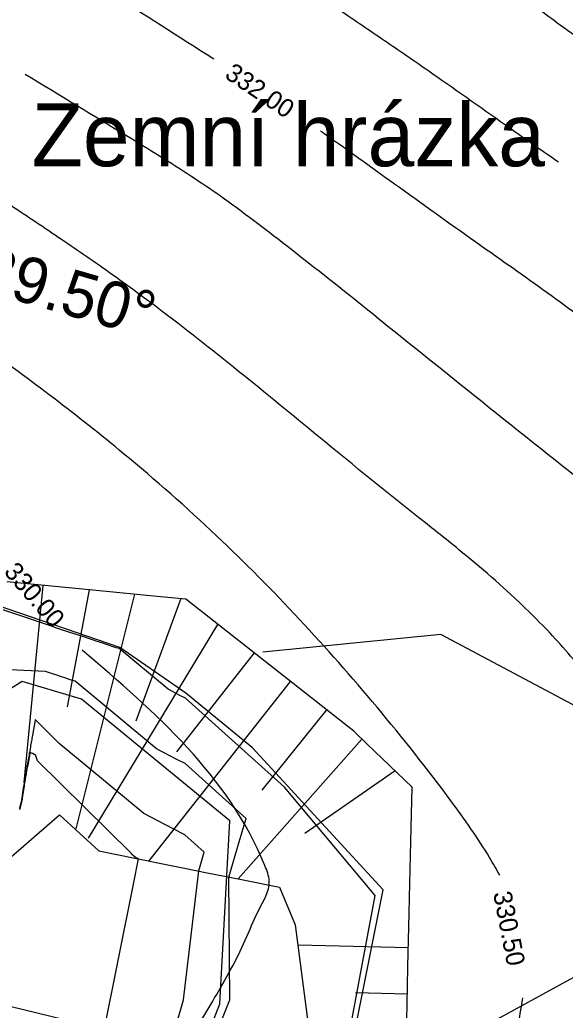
# Model space of a CAD drawing. Extents: x -564037 to -563827, y -1163561 to -1163412.
# Drawn here: x -563886.48 to -563871.67, y -1163493.12 to -1163466.24 of the extents above; entities that cross this region are included whole.
import ezdxf

# ---------------------------------------------------------------- set-up
doc = ezdxf.new("R2010")
doc.units = 0
for name, color, linetype in [('4', 7, 'Continuous'), ('5', 7, 'Continuous'), ('_popis staničení RT1', 7, 'Continuous'), ('Default', 7, 'Continuous'), ('Line', 7, 'Continuous'), ('Vrstva 24', 7, 'Continuous'), ('Vrstva 25', 7, 'Continuous'), ('Vrstva 26', 7, 'Continuous')]:
    doc.layers.add(name, color=color, linetype=linetype)

msp = doc.modelspace()

# ---------------------------------------------------------------- linework, layer by layer
for points in [[(-563900.324, -1163505.882), (-563892.678, -1163503.006), (-563888.735, -1163501.906), (-563886.271, -1163502.018), (-563883.536, -1163500.684), (-563878.095, -1163497.234), (-563876.621, -1163489.849), (-563880.163, -1163485.998), (-563881.977, -1163484.515), (-563883.765, -1163483.269), (-563890.133, -1163481.092), (-563891.974, -1163485.382), (-563895.143, -1163493.304), (-563898.704, -1163502.458), (-563900.439, -1163505.855)], [(-563887.058, -1163484.593), (-563887.855, -1163487.81), (-563890.21, -1163493.633), (-563891.581, -1163498.253), (-563891.461, -1163499.576), (-563890.275, -1163499.82), (-563886.599, -1163499.649), (-563882.84, -1163497.558), (-563881.049, -1163492.941), (-563880.784, -1163487.979), (-563884.81, -1163484.679), (-563886.418, -1163484.198)]]:
    msp.add_lwpolyline(points, close=True)
for points in [[(-563878.137, -1163496.97), (-563876.837, -1163490), (-563879.296, -1163487.066), (-563881.987, -1163484.651), (-563882.119, -1163484.582), (-563882.455, -1163484.408), (-563883.788, -1163483.304), (-563883.864, -1163483.279), (-563884.159, -1163483.181), (-563884.226, -1163483.159), (-563884.302, -1163483.134), (-563884.34, -1163483.121), (-563884.386, -1163483.106), (-563884.482, -1163483.074), (-563884.592, -1163483.038), (-563884.718, -1163482.996), (-563884.865, -1163482.947), (-563884.978, -1163482.91), (-563885.376, -1163482.786), (-563885.4, -1163482.777), (-563885.486, -1163482.747), (-563885.596, -1163482.707), (-563890.151, -1163481.173)], [(-563866.782, -1163487.32), (-563875.054, -1163482.917), (-563879.887, -1163483.398)], [(-563882.19, -1163496.364), (-563880.778, -1163492.835), (-563880.808, -1163489.502), (-563880.527, -1163488.546), (-563880.34, -1163487.91), (-563881.995, -1163486.424), (-563882.215, -1163486.31), (-563882.772, -1163486.021), (-563884.984, -1163484.19), (-563885.111, -1163484.148), (-563885.233, -1163484.108), (-563885.348, -1163484.069), (-563885.478, -1163484.026), (-563885.544, -1163484.004), (-563885.623, -1163483.978), (-563885.788, -1163483.923), (-563887.164, -1163483.863), (-563888.153, -1163487.579), (-563890.867, -1163493.518)], [(-563883.008, -1163496.199), (-563882.04, -1163492.836), (-563881.625, -1163489.337), (-563881.476, -1163488.829), (-563882.005, -1163488.354), (-563882.32, -1163488.191), (-563883.117, -1163487.777), (-563885.412, -1163485.878), (-563885.848, -1163485.443), (-563886.064, -1163485.228), (-563886.076, -1163485.297), (-563886.076, -1163485.299), (-563886.085, -1163485.349), (-563886.086, -1163485.357), (-563886.119, -1163485.544), (-563886.123, -1163485.565), (-563886.154, -1163485.739), (-563886.159, -1163485.771), (-563886.188, -1163485.934), (-563886.195, -1163485.977), (-563886.222, -1163486.129), (-563886.225, -1163486.143), (-563886.233, -1163486.193), (-563886.255, -1163486.313), (-563886.255, -1163486.317), (-563886.275, -1163486.425), (-563886.283, -1163486.475), (-563886.288, -1163486.503), (-563886.291, -1163486.518), (-563886.312, -1163486.636), (-563886.324, -1163486.708), (-563886.339, -1163486.796), (-563886.352, -1163486.873), (-563886.356, -1163486.898), (-563886.367, -1163486.965), (-563886.38, -1163487.043), (-563886.387, -1163487.088), (-563886.417, -1163487.278), (-563886.42, -1163487.295), (-563886.422, -1163487.306), (-563886.427, -1163487.341), (-563886.437, -1163487.403), (-563886.447, -1163487.469), (-563886.478, -1163487.59), (-563886.495, -1163487.654)], [(-563884.64, -1163495.87), (-563883.396, -1163489.693), (-563883.258, -1163489.008), (-563883.35, -1163488.961), (-563883.403, -1163488.916), (-563883.413, -1163488.906), (-563883.424, -1163488.896), (-563883.429, -1163488.891), (-563883.454, -1163488.866), (-563886.003, -1163486.346), (-563886.061, -1163486.188), (-563886.092, -1163486.174), (-563886.139, -1163486.152), (-563886.207, -1163486.12), (-563886.209, -1163486.131), (-563886.213, -1163486.15), (-563886.213, -1163486.152), (-563886.242, -1163486.315), (-563886.242, -1163486.316), (-563886.269, -1163486.463), (-563886.271, -1163486.477), (-563886.278, -1163486.515), (-563886.279, -1163486.52), (-563886.307, -1163486.681), (-563886.312, -1163486.71), (-563886.334, -1163486.831), (-563886.339, -1163486.866), (-563886.345, -1163486.9), (-563886.36, -1163486.992), (-563886.366, -1163487.027), (-563886.376, -1163487.09), (-563886.4, -1163487.252), (-563886.405, -1163487.28), (-563886.409, -1163487.304), (-563886.409, -1163487.308), (-563886.417, -1163487.357), (-563886.421, -1163487.379), (-563886.435, -1163487.472), (-563886.478, -1163487.642), (-563886.482, -1163487.657), (-563886.488, -1163487.679)], [(-563889.53, -1163495.82), (-563888.841, -1163493.998), (-563888.841, -1163493.998), (-563888.841, -1163493.998), (-563887.797, -1163491.659), (-563887.07, -1163489.251), (-563885.406, -1163487.811), (-563884.336, -1163488.791), (-563884.336, -1163488.791), (-563884.336, -1163488.791), (-563883.356, -1163488.989), (-563882.375, -1163489.186), (-563882.009, -1163489.26), (-563881.395, -1163489.384), (-563880.687, -1163489.526), (-563880.415, -1163489.581), (-563879.434, -1163489.779), (-563879.009, -1163490.8), (-563878.655, -1163493.506)]]:
    msp.add_lwpolyline(points)
at = {"layer": '5'}
for p, q in [((-563897.15, -1163506.247), (-563862.812, -1163487.513)), ((-563904.23, -1163488.796), (-563873.359, -1163496.24))]:
    msp.add_line(p, q, dxfattribs=at)
at = {"layer": 'Default'}
msp.add_lwpolyline([(-563875.979, -1163493.391), (-563875.957, -1163492.484), (-563875.943, -1163491.921), (-563875.909, -1163490.489), (-563875.899, -1163490.06), (-563875.853, -1163488.158), (-563875.827, -1163487.061), (-563877.051, -1163485.894), (-563877.417, -1163485.546), (-563881.974, -1163481.961), (-563882.667, -1163481.894), (-563884.497, -1163481.718), (-563886.832, -1163481.493)], dxfattribs=at)
at = {"layer": 'Line'}
for p, q in [((-563886.362, -1163486.934), (-563885.847, -1163481.588)), ((-563884.602, -1163481.708), (-563885.193, -1163484.881)), ((-563884.948, -1163488.198), (-563883.358, -1163481.827)), ((-563882.114, -1163481.947), (-563883.329, -1163485.273)), ((-563884.614, -1163488.443), (-563881.102, -1163482.646)), ((-563880.12, -1163483.419), (-563882.231, -1163486.103)), ((-563882.972, -1163489.066), (-563879.137, -1163484.192)), ((-563878.155, -1163484.965), (-563879.913, -1163487.147)), ((-563880.557, -1163489.552), (-563877.192, -1163485.76)), ((-563876.287, -1163486.623), (-563878.747, -1163488.324)), ((-563875.931, -1163491.424), (-563878.937, -1163491.352)), ((-563877.367, -1163492.64), (-563875.961, -1163492.674))]:
    msp.add_line(p, q, dxfattribs=at)
at = {"layer": 'Vrstva 24'}
for points in [[(-563881.219, -1163467.306), (-563886.923, -1163463.69), (-563888.12, -1163462.966), (-563888.746, -1163462.613), (-563889.58, -1163462.16), (-563890.418, -1163461.713), (-563891.255, -1163461.265), (-563892.088, -1163460.81), (-563893.666, -1163459.845), (-563894.43, -1163459.321), (-563895.185, -1163458.779), (-563896.456, -1163457.801), (-563897.673, -1163456.767), (-563898.845, -1163455.679), (-563899.977, -1163454.537), (-563900.905, -1163453.498), (-563901.733, -1163452.383), (-563902.044, -1163451.876), (-563902.327, -1163451.358), (-563902.78, -1163450.276), (-563904.206, -1163445.764), (-563905.71, -1163441.12)], [(-563862.955, -1163472.882), (-563865.358, -1163470.941), (-563867.276, -1163469.557), (-563868.391, -1163468.776), (-563869.51, -1163468.001), (-563870.628, -1163467.223), (-563871.739, -1163466.436), (-563872.344, -1163465.986), (-563877.172, -1163462.238), (-563879.042, -1163460.73), (-563880.713, -1163459.293), (-563882.35, -1163457.816), (-563883.983, -1163456.336), (-563885.646, -1163454.889), (-563886.028, -1163454.584), (-563886.155, -1163454.491), (-563886.219, -1163454.446), (-563886.25, -1163454.423), (-563886.266, -1163454.411)], [(-563866.364, -1163497.311), (-563866.075, -1163496.511), (-563865.895, -1163495.533), (-563865.845, -1163494.553), (-563865.947, -1163493.507), (-563866.272, -1163492.388), (-563866.563, -1163491.699), (-563866.868, -1163491.02), (-563867.192, -1163490.352), (-563867.536, -1163489.691), (-563869.125, -1163486.92), (-563869.85, -1163485.772), (-563870.624, -1163484.653), (-563871.666, -1163483.346), (-563872.824, -1163482.142), (-563874.562, -1163480.618), (-563875.472, -1163479.893), (-563878.363, -1163477.556), (-563882.755, -1163474.046), (-563884.234, -1163472.969), (-563885.61, -1163472.026), (-563886.998, -1163471.1), (-563889.83, -1163469.34), (-563892.347, -1163467.891)], [(-563852.947, -1163500.287), (-563852.983, -1163499.934), (-563853.278, -1163497.907), (-563853.324, -1163497.501), (-563853.384, -1163496.604), (-563853.408, -1163496.155), (-563853.449, -1163495.707), (-563853.76, -1163494.797), (-563854.364, -1163493.737), (-563856.816, -1163489.636), (-563859.313, -1163485.439), (-563859.915, -1163484.694), (-563860.397, -1163484.207), (-563862.509, -1163482.09), (-563867.011, -1163477.664), (-563868.116, -1163476.702), (-563871.116, -1163474.41), (-563872.986, -1163473.06), (-563873.689, -1163472.566), (-563878.103, -1163469.411), (-563878.316, -1163469.26)]]:
    msp.add_spline(points, degree=3, dxfattribs=at)
at = {"layer": 'Vrstva 25'}
msp.add_spline([(-563905.141, -1163510.37), (-563904.922, -1163510.229), (-563901.706, -1163508.177), (-563898.297, -1163505.868), (-563895.6, -1163504.013), (-563893.249, -1163502.324), (-563892.081, -1163501.469), (-563890.919, -1163500.608), (-563889.757, -1163499.746), (-563888.589, -1163498.892), (-563887.491, -1163498.145), (-563886.364, -1163497.441), (-563885.229, -1163496.747), (-563884.107, -1163496.03), (-563883.48, -1163495.59), (-563883.181, -1163495.349), (-563882.893, -1163495.092), (-563882.209, -1163494.336), (-563881.626, -1163493.502), (-563881.193, -1163492.783), (-563880.36, -1163491.213), (-563880.004, -1163490.417), (-563879.711, -1163489.616), (-563879.829, -1163489.186), (-563884.789, -1163483.345)], degree=3, dxfattribs=at)
at = {"layer": 'Vrstva 26'}
for points in [[(-563871.856, -1163470.105), (-563873.031, -1163469.285), (-563875.156, -1163467.789), (-563876.357, -1163466.959), (-563877.564, -1163466.138), (-563878.77, -1163465.315), (-563879.967, -1163464.48), (-563881.537, -1163463.354), (-563887.187, -1163459.271), (-563890.237, -1163457.354), (-563891.792, -1163456.442), (-563893.339, -1163455.518), (-563894.167, -1163455.001), (-563894.589, -1163454.631), (-563894.918, -1163454.179), (-563895.238, -1163453.557), (-563895.54, -1163452.929), (-563896.062, -1163451.643), (-563896.672, -1163449.878), (-563897.273, -1163448.112), (-563898.405, -1163444.558), (-563898.83, -1163443.13)], [(-563873.45, -1163489.454), (-563873.727, -1163488.976), (-563874.776, -1163487.436), (-563876.784, -1163484.893), (-563881.14, -1163480.242), (-563883.664, -1163478.013), (-563887.513, -1163475.075), (-563890.545, -1163473.024), (-563896.225, -1163469.436), (-563897.371, -1163468.706), (-563897.941, -1163468.337), (-563899.477, -1163467.352), (-563904.895, -1163463.746), (-563905.311, -1163463.453)], [(-563859.41, -1163497.306), (-563859.213, -1163496.32), (-563859.173, -1163495.343), (-563859.23, -1163495.062), (-563859.315, -1163494.786), (-563859.559, -1163494.264), (-563860.664, -1163492.33), (-563861.767, -1163490.395), (-563863.612, -1163487.077), (-563864.619, -1163485.435), (-563865.167, -1163484.642), (-563865.744, -1163483.864), (-563868.01, -1163481.46), (-563871.348, -1163478.665), (-563874.529, -1163476.131), (-563879.25, -1163472.365), (-563881.038, -1163471.025), (-563881.839, -1163470.479), (-563883.542, -1163469.415), (-563886.341, -1163467.718)], [(-563906.28, -1163515.803), (-563905.884, -1163515.571), (-563902.883, -1163513.741), (-563899.929, -1163512.038), (-563897.928, -1163511.018), (-563895.553, -1163509.778), (-563893.055, -1163508.246), (-563892.353, -1163507.782), (-563891.657, -1163507.311), (-563890.96, -1163506.841), (-563890.257, -1163506.379), (-563888.16, -1163505.094), (-563886.21, -1163504.031), (-563880.965, -1163501.085), (-563878.454, -1163499.578), (-563877.23, -1163498.772), (-563876.032, -1163497.922), (-563874.901, -1163496.941), (-563873.614, -1163495.651), (-563873.276, -1163495.107), (-563873.154, -1163494.587), (-563873.048, -1163494.066), (-563872.865, -1163493.019), (-563872.827, -1163492.778)]]:
    msp.add_spline(points, degree=3, dxfattribs=at)

# ---------------------------------------------------------------- texts
at = {"layer": '4'}
msp.add_text('Zemní hrázka PH3', height=1.70472, rotation=360, dxfattribs=at).set_placement((-563886.162, -1163470.212))
at = {"layer": '_popis staničení RT1'}
msp.add_text('R=5m alfa=89.50%%d', height=1.25, rotation=343.8679, dxfattribs=at).set_placement((-563895.987, -1163471.129))
at = {"layer": 'Vrstva 25'}
for s, rotation, p in [('332.00', 326.0566, (-563880.949, -1163467.793)), ('330.00', 310.6836, (-563886.936, -1163481.23)), ('330.50', 280.9781, (-563873.634, -1163489.939))]:
    msp.add_text(s, height=0.5, rotation=rotation, dxfattribs=at).set_placement(p)

doc.saveas('drawing.dxf')
